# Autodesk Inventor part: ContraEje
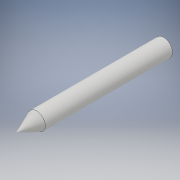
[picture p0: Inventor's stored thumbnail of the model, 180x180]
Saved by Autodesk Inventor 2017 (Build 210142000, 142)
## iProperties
Part Number: ContraEje
Material: Genérico
Document SubType Name: Modeling
Designer: Diego
Density: 1 g/cm^3
Appearance: Valor por defecto
Author: Diego
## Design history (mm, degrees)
derived "Lubina.ipt"
feature "Sólido16::Lubina.ipt" dims "d0" = 10
tag "OperaciónIdentificador1"
node "Sólido1"
